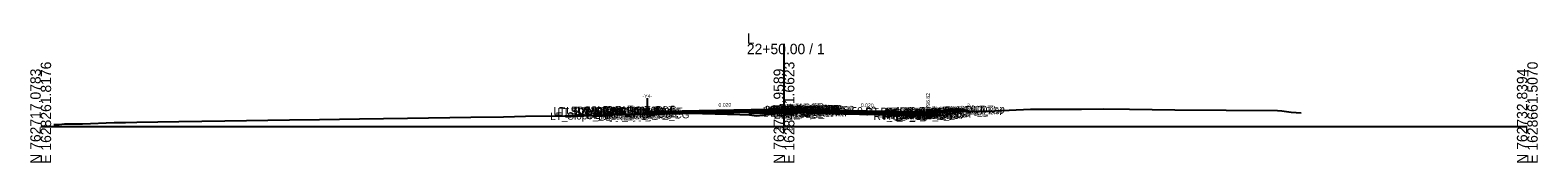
# Model space of a CAD drawing. Extents: x -26 to 4403, y -510 to 9556.
# Drawn here: x 997.2 to 1402.8, y 2490.3 to 2525.1 of the extents above; entities that cross this region are included whole.
import ezdxf

# ---------------------------------------------------------------- set-up
doc = ezdxf.new("R2010")
doc.units = 0
for name, color, linetype in [('Default', 7, 'Continuous'), ('Exist CMT Pavement', 7, 'Continuous'), ('Exist Cross Section Cell', 7, 'Continuous'), ('Exist XS Center Line Elevation Label', 7, 'Continuous'), ('Exist XS Ground Line', 7, 'Continuous'), ('Prop CMT Conc Surface', 7, 'Continuous'), ('Prop CMT Concrete Structures', 7, 'Continuous'), ('Prop CMT Pvmt Course 1', 7, 'Continuous'), ('Prop CMT Pvmt Course 1 CG', 7, 'Continuous'), ('Prop CMT Pvmt Course 2', 7, 'Continuous'), ('Prop CMT Pvmt Course 3', 7, 'Continuous'), ('Prop CMT Pvmt Surface', 7, 'Continuous'), ('Prop CMT Shear Line', 7, 'Continuous'), ('Prop CMT Slope Grass', 7, 'Continuous'), ('Prop CMT Subgrade Earthwork', 7, 'Continuous'), ('Prop XS Hydro Elevations', 7, 'Continuous'), ('Prop XS SE Text', 7, 'Continuous'), ('Prop XS Side Slope Text', 7, 'Continuous'), ('Scratch_Level_0', 7, 'Continuous')]:
    doc.layers.add(name, color=color, linetype=linetype)

msp = doc.modelspace()

# ---------------------------------------------------------------- linework, layer by layer
at = {"layer": 'Exist CMT Pavement'}
msp.add_lwpolyline([(1163.25, 2503.46), (1171.42, 2503.67), (1188.13, 2503.25), (1190.7, 2503.18)], dxfattribs=at)
at = {"layer": 'Exist Cross Section Cell'}
for p, q in [((1200, 2500), (1200, 2522.29)), ((1000, 2500), (1200, 2500)), ((1200, 2500), (1400, 2500))]:
    msp.add_line(p, q, dxfattribs=at)
at = {"layer": 'Exist XS Ground Line'}
msp.add_lwpolyline([(1003.53, 2500.6), (1004.97, 2500.61), (1006.36, 2500.75), (1011.21, 2500.77), (1019.72, 2501.15), (1022.77, 2501.13), (1025.87, 2501.23), (1037.12, 2501.4), (1049.53, 2501.56), (1066.93, 2501.81), (1075.03, 2501.92), (1085.81, 2502.08), (1098.65, 2502.27), (1115.71, 2502.53), (1124.51, 2502.66), (1130.48, 2502.77), (1141.06, 2502.9), (1146.17, 2502.94), (1147.14, 2502.97), (1147.97, 2503), (1148.38, 2503.01), (1162.42, 2503.44), (1171.42, 2503.67), (1188.13, 2503.25), (1190.7, 2503.18), (1192.56, 2502.93), (1194.27, 2503.12), (1198.27, 2503.53), (1200, 2503.63), (1202.09, 2503.75), (1204.29, 2503.86), (1213.64, 2503.88), (1216.76, 2503.89), (1222.41, 2503.99), (1233.11, 2504.08), (1238.78, 2503.92), (1247.59, 2504.19), (1254.85, 2504.2), (1266.37, 2504.72), (1280.08, 2504.7), (1286.05, 2504.77), (1292.97, 2504.74), (1305.17, 2504.51), (1319.01, 2504.44), (1332.78, 2504.36), (1333.94, 2504.22), (1336.42, 2503.86), (1339.12, 2503.68)], dxfattribs=at)
at = {"layer": 'Prop CMT Conc Surface'}
for points in [[(1236.75, 2503.94), (1238.75, 2503.82)], [(1238.75, 2503.82), (1238.75, 2504.32), (1239.25, 2504.32)], [(1243.25, 2504.41), (1248.25, 2504.51)]]:
    msp.add_lwpolyline(points, dxfattribs=at)
at = {"layer": 'Prop CMT Concrete Structures'}
for points in [[(1163.25, 2503.36), (1163.25, 2503.94)], [(1208, 2504.51), (1207.99, 2504.68), (1207.24, 2504.93), (1206.53, 2505.21), (1205.81, 2505.19), (1205.06, 2504.94), (1205.05, 2504.78)], [(1205.05, 2504.78), (1208, 2504.51)], [(1236.75, 2503.94), (1238.75, 2503.82), (1238.75, 2504.32), (1239.25, 2504.32)], [(1239.25, 2504.32), (1239.25, 2503.31), (1236.75, 2503.36)], [(1236.75, 2503.36), (1236.75, 2503.94)], [(1248.25, 2504.51), (1243.25, 2504.41)], [(1243.25, 2504.41), (1243.25, 2504.08)], [(1243.25, 2504.08), (1248.25, 2504.18)], [(1248.25, 2504.18), (1248.25, 2504.51)]]:
    msp.add_lwpolyline(points, dxfattribs=at)
at = {"layer": 'Prop CMT Pvmt Course 1'}
for points in [[(1205.05, 2504.78), (1163.25, 2503.94)], [(1163.25, 2503.69), (1205.05, 2504.53)], [(1163.25, 2503.94), (1163.25, 2503.69)], [(1205.05, 2504.78), (1208, 2504.51)], [(1205.05, 2504.53), (1205.05, 2504.78)], [(1205.05, 2504.53), (1205.05, 2504.78)], [(1208, 2504.26), (1205.05, 2504.53)], [(1208, 2504.51), (1208, 2504.26)], [(1208, 2504.51), (1236.75, 2503.94)], [(1208, 2504.26), (1208, 2504.51)], [(1236.75, 2503.69), (1208, 2504.26)], [(1236.75, 2503.94), (1236.75, 2503.69)]]:
    msp.add_lwpolyline(points, dxfattribs=at)
for points in [[(1205.05, 2504.53), (1205.05, 2504.65), (1205.05, 2504.65), (1205.05, 2504.53)], [(1208, 2504.26), (1208, 2504.39), (1208, 2504.39), (1208, 2504.26)]]:
    msp.add_lwpolyline(points, close=True, dxfattribs=at)
at = {"layer": 'Prop CMT Pvmt Course 1 CG'}
for points in [[(1163.25, 2503.02), (1163.25, 2503.36)], [(1236.75, 2503.36), (1239.75, 2503.3), (1240.09, 2502.96)], [(1236.75, 2503.02), (1236.75, 2503.36)], [(1240.09, 2502.96), (1236.75, 2503.02)]]:
    msp.add_lwpolyline(points, dxfattribs=at)
at = {"layer": 'Prop CMT Pvmt Course 2'}
for points in [[(1205.05, 2504.53), (1163.25, 2503.69)], [(1163.25, 2503.36), (1205.05, 2504.19)], [(1163.25, 2503.69), (1163.25, 2503.36)], [(1205.05, 2504.53), (1208, 2504.26)], [(1205.05, 2504.19), (1205.05, 2504.53)], [(1205.05, 2504.19), (1205.05, 2504.53)], [(1208, 2503.93), (1205.05, 2504.19)], [(1208, 2504.26), (1208, 2503.93)], [(1208, 2503.93), (1208, 2504.26)], [(1208, 2504.26), (1236.75, 2503.69)], [(1236.75, 2503.36), (1208, 2503.93)], [(1236.75, 2503.69), (1236.75, 2503.36)]]:
    msp.add_lwpolyline(points, dxfattribs=at)
at = {"layer": 'Prop CMT Pvmt Course 3'}
for points in [[(1205.05, 2504.19), (1163.25, 2503.36)], [(1163.25, 2503.36), (1163.25, 2503.02)], [(1190.7, 2503.57), (1205.05, 2503.86)], [(1205.05, 2504.19), (1208, 2503.93)], [(1205.05, 2503.86), (1205.05, 2504.19)], [(1205.05, 2503.86), (1205.05, 2504.19)], [(1208, 2503.6), (1205.05, 2503.86)], [(1208, 2503.93), (1208, 2503.6)], [(1208, 2503.93), (1236.75, 2503.36)], [(1208, 2503.6), (1208, 2503.93)], [(1236.75, 2503.02), (1208, 2503.6)], [(1236.75, 2503.36), (1236.75, 2503.02)]]:
    msp.add_lwpolyline(points, dxfattribs=at)
at = {"layer": 'Prop CMT Pvmt Surface'}
for points in [[(1205.05, 2504.78), (1163.25, 2503.94)], [(1205.05, 2504.78), (1208, 2504.51)], [(1208, 2504.51), (1236.75, 2503.94)]]:
    msp.add_lwpolyline(points, dxfattribs=at)
at = {"layer": 'Prop CMT Shear Line'}
msp.add_line((1163.25, 2502.38), (1163.25, 2507.62), dxfattribs=at)
at = {"layer": 'Prop CMT Slope Grass'}
for points in [[(1239.25, 2504.32), (1248.25, 2504.5)], [(1248.25, 2504.5), (1248.75, 2504.51), (1249.7, 2504.19)]]:
    msp.add_lwpolyline(points, dxfattribs=at)
at = {"layer": 'Prop CMT Subgrade Earthwork'}
for p, q in [((1163.25, 2503.02), (1163.25, 2503.36)), ((1190.7, 2503.57), (1190.7, 2503.18))]:
    msp.add_line(p, q, dxfattribs=at)
for points in [[(1205.05, 2503.86), (1190.7, 2503.57)], [(1205.05, 2503.86), (1208, 2503.6)], [(1208, 2503.6), (1236.75, 2503.02)], [(1236.75, 2503.02), (1240.09, 2502.96), (1241.5, 2504.36)]]:
    msp.add_lwpolyline(points, dxfattribs=at)

# ---------------------------------------------------------------- texts
at = {"layer": 'Default'}
msp.add_text('-', height=0.0001, dxfattribs=at).set_placement((1000, 2500))
at = {"layer": 'Exist Cross Section Cell'}
for s, p in [('L', (1190, 2522.29)), ('22+50.00 / 1', (1190, 2519.49))]:
    msp.add_text(s, height=2.8, dxfattribs=at).set_placement(p)
for s, p in [('N 762717.0783', (1000, 2490)), ('E 1628261.8176', (1002.8, 2490)), ('N 762724.9589', (1200, 2490)), ('E 1628461.6623', (1202.8, 2490)), ('N 762732.8394', (1400, 2490)), ('E 1628661.5070', (1402.8, 2490))]:
    msp.add_text(s, height=2.8, rotation=90, dxfattribs=at).set_placement(p)
at = {"layer": 'Exist XS Center Line Elevation Label'}
msp.add_text('796.63', height=1.2, dxfattribs=at).set_placement((1197.47, 2499.03))
at = {"layer": 'Prop XS Hydro Elevations'}
for s, rotation, p in [('-Y4-', 360, (1161.92, 2507.7)), ('796.82', 90, (1239.25, 2504.82))]:
    msp.add_text(s, height=1, rotation=rotation, dxfattribs=at).set_placement(p)
at = {"layer": 'Prop XS SE Text'}
for rotation, p in [(1.1456, (1182.38, 2505.32)), (358.8543, (1220.65, 2505.26))]:
    msp.add_text('0.020', height=1, rotation=rotation, dxfattribs=at).set_placement(p)
at = {"layer": 'Prop XS Side Slope Text'}
msp.add_text('3:1', height=1, rotation=341.5651, dxfattribs=at).set_placement((1249.09, 2505.35))
at = {"layer": 'Scratch_Level_0'}
for s, p in [('LT_Slope_Fill', (1137.11, 2501.76)), ('LT_SDWK_Out_Top', (1138.01, 2503.23)), ('LT_SDWK_Out_Bot', (1138.04, 2502.9)), ('LT_Sub_Trench_Out_DLT', (1139.09, 2502.98)), ('LT_CSLP_Pnt', (1141.44, 2503.31)), ('22+50.00', (1143.76, 2503.12)), ('LT_SDWK_In_Top', (1144.63, 2503.17)), ('LT_SDWK_In_Bot', (1144.66, 2502.84)), ('LT_CG1_Shelf_Out', (1146.82, 2502.03)), ('LT_CG_Top_Face', (1148.53, 2503.07)), ('LT_CG_Top_BOC', (1149.06, 2503.09)), ('LT_CG_Bot_BOC', (1149.09, 2502.07)), ('LT_CG_Top_Gut', (1149.51, 2502.58)), ('LT_Sub_OEOP', (1150.04, 2501.76)), ('LT_Sub_OEOT_CG', (1150.64, 2501.77)), ('22+50.00', (1152.96, 2503.21)), ('LT_CG_Bot_IE', (1153.19, 2502.16)), ('LT_Sub_OEOT', (1153.35, 2501.83)), ('LT_PV2_OEOT', (1153.45, 2502.49)), ('LT_PV3_OEOT', (1153.45, 2502.16)), ('LT_PV1_OEOT', (1154.01, 2502.76)), ('22+50.00', (1154.43, 2503.19)), ('LT_Sub_OEEOP', (1194.29, 2502.64)), ('LT_PV2_OEEOP', (1194.38, 2503.31)), ('LT_PV3_OEEOP', (1194.38, 2502.98)), ('22+50.00', (1194.78, 2503.57)), ('LT_PV1_OEEOP', (1194.95, 2503.45)), ('LT_PV2_IEEOP', (1195.03, 2503.33)), ('LT_PV1_IEEOP', (1195.6, 2503.46)), ('LT_PV2_PGL1', (1195.96, 2503.34)), ('LT_PV3_PGL1', (1195.96, 2503.01)), ('LT_PV2_PGL', (1196.29, 2503.35)), ('LT_PV4_PGL', (1196.29, 2502.68)), ('LT_PV1_PGL', (1196.86, 2503.61)), ('MI_Face In', (1196.98, 2503.78)), ('RT_Sub_OEEOP', (1197.19, 2502.38)), ('RT_PV2_OEEOP', (1197.28, 2503.05)), ('RT_PV3_OEEOP', (1197.28, 2502.72)), ('RT_PV1_OEEOP', (1197.85, 2503.19)), ('RT_PV2_IEEOP', (1197.93, 2503.06)), ('MI_Face Out', (1198.28, 2503.49)), ('MI_Top Out', (1198.49, 2503.76)), ('RT_PV1_IEEOP', (1198.49, 2503.2)), ('MI_Top In', (1198.69, 2504.05)), ('RT_PV2_PGL1', (1198.86, 2503.08)), ('RT_PV3_PGL1', (1198.86, 2502.75)), ('22+50.00', (1198.99, 2504.03)), ('RT_PV2_PGL', (1199.19, 2503.09)), ('RT_PV4_PGL', (1199.19, 2502.42)), ('MI_Bot Out', (1199.28, 2503.34)), ('22+50.00', (1199.57, 2504.07)), ('MI_Crown', (1199.62, 2504.07)), ('RT_PV1_PGL', (1199.75, 2503.35)), ('22+50.00', (1200.73, 2503.72)), ('22+50.00', (1201.26, 2503.41)), ('22+50.00', (1213.69, 2503.13)), ('RT_Sub_Trench_Out_DLT', (1222.04, 2502.98)), ('RT_Sub_OEOT_CG', (1224.1, 2501.77)), ('RT_CG_Top_Face', (1225.99, 2503.06)), ('RT_CG1_Shelf_Out', (1226.28, 2502.03)), ('RT_CG_Bot_IE', (1226.64, 2502.15)), ('RT_Sub_OEOT', (1226.8, 2501.82)), ('RT_PV2_OEOT', (1226.9, 2502.49)), ('RT_PV3_OEOT', (1226.9, 2502.16)), ('RT_CG_Top_Gut', (1226.96, 2502.58)), ('RT_PV1_OEOT', (1227.47, 2502.75)), ('RT_CG_Top_BOC', (1227.51, 2503.08)), ('RT_CG_Bot_BOC', (1227.54, 2502.07)), ('RT_Sub_OEOP', (1230.17, 2501.76)), ('RT_SDWK_In_Top', (1231.08, 2503.17)), ('RT_SDWK_In_Bot', (1231.12, 2502.83)), ('22+50.00', (1232.2, 2503.19)), ('RT_SDWK_Out_Top', (1234.46, 2503.23)), ('RT_SDWK_Out_Bot', (1234.49, 2502.9)), ('RT_Slope_Fill', (1240.19, 2503)), ('RT_Shld_O', (1240.81, 2503.35)), ('22+50.00', (1241.57, 2503.38)), ('CSLP_Pnt', (1241.64, 2503.37)), ('22+50.00', (1242.66, 2503.16))]:
    msp.add_text(s, height=2, rotation=1.1458, dxfattribs=at).set_placement(p)

doc.saveas('drawing.dxf')
